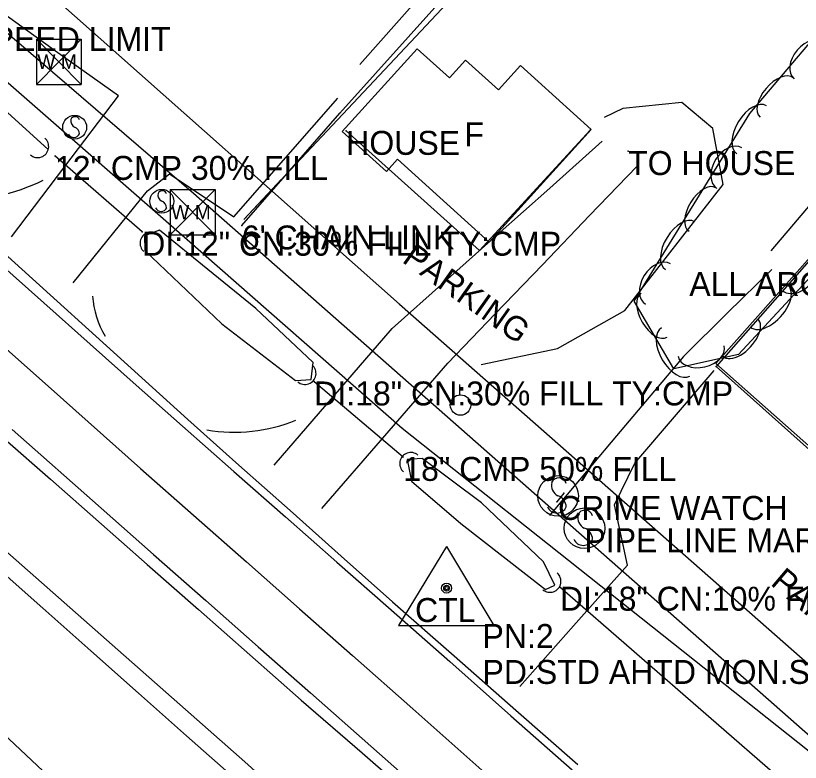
# Model space of a CAD drawing. Extents: x 1441650 to 1491889, y 345904 to 358319.
# Drawn here: x 1443948.5 to 1444112.3, y 355867 to 356022.9 of the extents above; entities that cross this region are included whole.
import ezdxf

# ---------------------------------------------------------------- set-up
doc = ezdxf.new("R2010")
doc.units = 0
for name, color, linetype in [('S_BUILDING', 7, 'Continuous'), ('S_BUILDING_ANNOT', 7, 'Continuous'), ('S_CROSS_DRAIN', 7, 'Continuous'), ('S_CROSS_DRAIN_ANNOT', 7, 'Continuous'), ('S_DITCHLINE', 7, 'Continuous'), ('S_DRG_PT_SYM', 7, 'Continuous'), ('S_EDGE_PAVEMENT', 7, 'Continuous'), ('S_FENCE', 7, 'Continuous'), ('S_FENCE_ANNOT', 7, 'Continuous'), ('S_GAS_UTILITIES', 7, 'Continuous'), ('S_GRAVEL_ROAD', 7, 'Continuous'), ('S_MSC_PT_SYM', 7, 'Continuous'), ('S_PARKING', 7, 'Continuous'), ('S_PARKING_ANNOT', 7, 'Continuous'), ('S_PAVEMENT_CROWN', 7, 'Continuous'), ('S_PRIMARY_CTL', 7, 'Continuous'), ('S_PRIMARY_CTL_ANNOT', 7, 'Continuous'), ('S_SANITARY_SEWER', 7, 'Continuous'), ('S_SHOULDER', 7, 'Continuous'), ('S_SIGN', 7, 'Continuous'), ('S_SIGN_ANNOT', 7, 'Continuous'), ('S_STR_PT_SYM', 7, 'Continuous'), ('S_STREAM', 7, 'Continuous'), ('S_SURVEY_TEXT_ANNOT', 7, 'Continuous'), ('S_TREE', 7, 'Continuous'), ('S_UTILITY_POLE', 7, 'Continuous'), ('S_UTL_PT_SYM', 7, 'Continuous'), ('S_WATER_UTILITIES', 7, 'Continuous')]:
    doc.layers.add(name, color=color, linetype=linetype)

msp = doc.modelspace()

# ---------------------------------------------------------------- linework, layer by layer
at = {"layer": 'S_BUILDING'}
for p, q in [((1444146.12, 356008.07), (1444094.68, 355949.69)), ((1444017.47, 355998.87), (1444045.28, 355973.87)), ((1444045.28, 355973.87), (1444068.39, 355999.05)), ((1444094.68, 355949.69), (1444124.92, 355922.65))]:
    msp.add_line(p, q, dxfattribs=at)
for points in [[(1444028.2, 355992.97), (1444047.33, 355975.65), (1444068.59, 355999.14), (1444053.84, 356012.49), (1444049.26, 356007.43), (1444042.38, 356013.66), (1444039.01, 356009.93), (1444032.29, 356016.01), (1444016.66, 355998.74), (1444025.88, 355990.4)], [(1444147.71, 356010.18), (1444094.63, 355950.31), (1444125.52, 355922.93), (1444178.59, 355982.81)]]:
    msp.add_lwpolyline(points, close=True, dxfattribs=at)
at = {"layer": 'S_CROSS_DRAIN'}
for p, q in [((1443974.88, 355977.81), (1443956.66, 355993.64)), ((1444010.79, 355946.55), (1444029.39, 355930.8)), ((1444062.09, 355903.7), (1444133.67, 355841.44))]:
    msp.add_line(p, q, dxfattribs=at)
for centre, start, end in [((1443953.06, 355995.6), 229.3018, 49.631), ((1443976.73, 355975.44), 49.3018, 229.631), ((1444008.87, 355948.24), 229.3018, 49.631), ((1444030.94, 355929.43), 49.3018, 229.631), ((1444060.01, 355904.83), 229.3018, 49.631)]:
    msp.add_arc(centre, 2.3, start, end, dxfattribs=at)
at = {"layer": 'S_DITCHLINE'}
for points in [[(1443680.55, 356237.92), (1443694.76, 356224.43), (1443704.6, 356215.46), (1443714.45, 356206.48), (1443724.29, 356197.51), (1443734.14, 356188.54), (1443743.98, 356179.56), (1443753.82, 356170.59), (1443763.67, 356161.61), (1443773.51, 356152.64), (1443791.44, 356137.07), (1443809.37, 356121.49), (1443827.3, 356105.92), (1443845.23, 356090.35), (1443857.24, 356080), (1443869.26, 356069.66), (1443881.27, 356059.31), (1443893.28, 356048.97), (1443905.29, 356038.62), (1443917.31, 356028.27), (1443929.32, 356017.93), (1443941.33, 356007.58), (1443955.28, 355994.97)], [(1443826.55, 356014.88), (1443833.1, 356010), (1443843.48, 356000.98), (1443853.85, 355991.95), (1443864.23, 355982.93), (1443874.61, 355973.9), (1443884.99, 355964.88), (1443895.37, 355955.85), (1443905.75, 355946.83), (1443916.13, 355937.8), (1443926.15, 355928.97), (1443936.17, 355920.13), (1443946.2, 355911.3), (1443956.22, 355902.47), (1443966.25, 355893.63), (1443976.27, 355884.8), (1443986.3, 355875.97), (1443996.32, 355867.13), (1444014.12, 355851.09), (1444031.92, 355835.05), (1444034.69, 355828.12)], [(1443825.3, 356012.13), (1443831.07, 356008.03), (1443841.45, 355998.86), (1443851.83, 355989.7), (1443862.2, 355980.53), (1443872.58, 355971.37), (1443882.96, 355962.2), (1443893.34, 355953.04), (1443903.72, 355943.87), (1443914.1, 355934.71), (1443924.1, 355925.83), (1443934.11, 355916.96), (1443944.12, 355908.09), (1443954.13, 355899.22), (1443964.13, 355890.35), (1443974.14, 355881.47), (1443984.15, 355872.6), (1443994.15, 355863.73), (1444010.59, 355846.19), (1444027.03, 355828.64), (1444031.97, 355825.21)], [(1444106.31, 355969.94), (1444097.09, 355960.86), (1444087.88, 355951.78), (1444073.9, 355935.18), (1444059.93, 355918.58)]]:
    msp.add_lwpolyline(points, dxfattribs=at)
for points in [[(1443978.52, 355978.11), (1443975.37, 355976.98), (1443975.4, 355973.87), (1443991.5, 355958.58), (1444006.86, 355946.74), (1444010.19, 355947), (1444010.6, 355950.53), (1443998.59, 355961.77), (1443988.55, 355969.94)], [(1444061.01, 355904.02), (1444058.68, 355908.93), (1444045.74, 355921.23), (1444033.32, 355930.5), (1444030.23, 355930.23), (1444031.13, 355925.71), (1444041.38, 355916.93), (1444059.11, 355903.15)]]:
    msp.add_lwpolyline(points, close=True, dxfattribs=at)
at = {"layer": 'S_DRG_PT_SYM'}
for points in [[(1443956.66, 355993.64), (1443956.66, 355993.69), (1443956.66, 355993.64), (1443956.61, 355993.64), (1443956.66, 355993.64), (1443956.66, 355993.59), (1443956.66, 355993.64), (1443956.71, 355993.64)], [(1443974.88, 355977.81), (1443974.88, 355977.86), (1443974.88, 355977.81), (1443974.83, 355977.81), (1443974.88, 355977.81), (1443974.88, 355977.76), (1443974.88, 355977.81), (1443974.93, 355977.81)], [(1444010.79, 355946.55), (1444010.79, 355946.6), (1444010.79, 355946.55), (1444010.74, 355946.55), (1444010.79, 355946.55), (1444010.79, 355946.5), (1444010.79, 355946.55), (1444010.84, 355946.55)], [(1444029.39, 355930.8), (1444029.39, 355930.85), (1444029.39, 355930.8), (1444029.34, 355930.8), (1444029.39, 355930.8), (1444029.39, 355930.75), (1444029.39, 355930.8), (1444029.44, 355930.8)], [(1444062.09, 355903.7), (1444062.09, 355903.75), (1444062.09, 355903.7), (1444062.04, 355903.7), (1444062.09, 355903.7), (1444062.09, 355903.65), (1444062.09, 355903.7), (1444062.14, 355903.7)]]:
    msp.add_lwpolyline(points, dxfattribs=at)
at = {"layer": 'S_EDGE_PAVEMENT'}
for points in [[(1443944.7, 355971.51), (1443954.35, 355962.94), (1443964, 355954.36), (1443973.65, 355945.79), (1443983.29, 355937.22), (1443994.04, 355927.76), (1444004.79, 355918.3), (1444015.54, 355908.83), (1444026.29, 355899.37), (1444039.08, 355888.06), (1444051.87, 355876.75), (1444064.66, 355865.45)], [(1443947.7, 355936.5), (1443966.34, 355920.1), (1443977.26, 355910.45), (1443988.18, 355900.81), (1443999.09, 355891.17), (1444010.01, 355881.53), (1444022.6, 355870.39), (1444035.18, 355859.26)]]:
    msp.add_lwpolyline(points, dxfattribs=at)
at = {"layer": 'S_FENCE'}
for p, q in [((1444016.14, 356002.59), (1444095, 356090.34)), ((1443995.68, 355979.12), (1444016.14, 356002.59))]:
    msp.add_line(p, q, dxfattribs=at)
for points in [[(1444095.65, 356092.67), (1444041.75, 356028.99), (1443996.1, 355980.38)], [(1444003.99, 355988.78), (1443996.1, 355980.38)]]:
    msp.add_lwpolyline(points, dxfattribs=at)
at = {"layer": 'S_GAS_UTILITIES'}
for p, q in [((1443849.94, 356102.4), (1443985.61, 355985.85)), ((1443985.61, 355985.85), (1444831.24, 355240.87))]:
    msp.add_line(p, q, dxfattribs=at)
at = {"layer": 'S_GRAVEL_ROAD'}
for points in [[(1443947.57, 355976.72), (1443958.75, 355991.45), (1443969.93, 356006.18), (1443957.29, 356015.2), (1443944.64, 356024.21), (1443932, 356033.22), (1443919.36, 356042.23), (1443907.76, 356051.97), (1443896.15, 356061.71), (1443884.55, 356071.46), (1443872.95, 356081.2), (1443854.94, 356094.72), (1443869.55, 356111.24), (1443884.15, 356127.77), (1443897.18, 356130.17), (1443918.05, 356122.57), (1443938.92, 356114.97)], [(1443960.49, 355967.18), (1443975.99, 355986.38), (1443980.58, 355989.9), (1443993.99, 355980.96), (1444004.86, 355993.34), (1444015.73, 356005.72)], [(1444002.4, 355929.1), (1444014.72, 355943.35), (1444027.04, 355957.6), (1444038.01, 355967.37), (1444048.99, 355977.15), (1444059.96, 355986.92), (1444070.93, 355996.7)], [(1444012.37, 355920.06), (1444025.54, 355935.23), (1444038.71, 355950.4), (1444048.56, 355960.67), (1444058.42, 355970.93), (1444068.27, 355981.2), (1444078.13, 355991.47)], [(1444053.74, 355882.87), (1444064.95, 355895.53), (1444076.17, 355908.2), (1444073.46, 355920.79), (1444077.75, 355929.52), (1444086.02, 355939.18), (1444094.3, 355948.84)]]:
    msp.add_lwpolyline(points, dxfattribs=at)
at = {"layer": 'S_MSC_PT_SYM'}
for points in [[(1444016.14, 356002.59), (1444016.14, 356002.64), (1444016.14, 356002.59), (1444016.09, 356002.59), (1444016.14, 356002.59), (1444016.14, 356002.54), (1444016.14, 356002.59), (1444016.19, 356002.59)], [(1444076.33, 355994.65), (1444076.33, 355994.7), (1444076.33, 355994.65), (1444076.28, 355994.65), (1444076.33, 355994.65), (1444076.33, 355994.6), (1444076.33, 355994.65), (1444076.38, 355994.65)], [(1443995.68, 355979.12), (1443995.68, 355979.17), (1443995.68, 355979.12), (1443995.63, 355979.12), (1443995.68, 355979.12), (1443995.68, 355979.07), (1443995.68, 355979.12), (1443995.73, 355979.12)], [(1444062.91, 355923.22), (1444062.91, 355923.27), (1444062.91, 355923.22), (1444062.86, 355923.22), (1444062.91, 355923.22), (1444062.91, 355923.17), (1444062.91, 355923.22), (1444062.96, 355923.22)], [(1444061.48, 355921.42), (1444061.48, 355921.47), (1444061.48, 355921.42), (1444061.43, 355921.42), (1444061.48, 355921.42), (1444061.48, 355921.37), (1444061.48, 355921.42), (1444061.53, 355921.42)]]:
    msp.add_lwpolyline(points, dxfattribs=at)
at = {"layer": 'S_PARKING'}
for points in [[(1444059.43, 356066.34), (1444064.08, 356062.11), (1444020.32, 356012.75)], [(1444045.68, 355950.13), (1444061.62, 355953.41), (1444075.63, 355961.34), (1444096.14, 355987.66), (1444094.05, 355999.37), (1444087.55, 356004.82), (1444075.2, 356003.53), (1444071.34, 356001.64)]]:
    msp.add_lwpolyline(points, dxfattribs=at)
for centre, major_axis, ratio, start_param, end_param in [((1443935.86, 356026.93), (38.83, 20.8), 0.965216, 4.220444, 4.668072), ((1443983.02, 355965.48), (-13.68, 12.57), 0.993891, 0.806764, 1.282027), ((1443994.12, 355970.42), (7.62, -33.61), 0.998476, 5.893169, 6.443204)]:
    msp.add_ellipse(centre, major_axis=major_axis, ratio=ratio, start_param=start_param, end_param=end_param, dxfattribs=at)
at = {"layer": 'S_PAVEMENT_CROWN'}
msp.add_lwpolyline([(1443937.16, 355961.6), (1443955.85, 355945), (1443974.54, 355928.4), (1443985.61, 355918.63), (1443996.68, 355908.87), (1444007.75, 355899.1), (1444018.81, 355889.33), (1444031.35, 355878.21), (1444043.89, 355867.08), (1444056.43, 355855.96)], dxfattribs=at)
at = {"layer": 'S_PRIMARY_CTL'}
for p, q in [((1444038.43, 355912.11), (1444028.4, 355895.6)), ((1444038.43, 355912.11), (1444048.26, 355895.6)), ((1444028.4, 355895.6), (1444048.26, 355895.6))]:
    msp.add_line(p, q, dxfattribs=at)
for radius in [1.04, 0.609, 0.344]:
    msp.add_circle((1444038.43, 355903.41), radius, dxfattribs=at)
at = {"layer": 'S_SANITARY_SEWER'}
for p, q in [((1443870.49, 356103.13), (1444028.57, 355962.69)), ((1443781.62, 356027.57), (1443955.36, 355864.1)), ((1444028.57, 355962.69), (1444201.27, 355810.66))]:
    msp.add_line(p, q, dxfattribs=at)
at = {"layer": 'S_SHOULDER'}
for points in [[(1443946.06, 355973.35), (1443955.64, 355964.67), (1443965.23, 355955.99), (1443974.82, 355947.31), (1443984.41, 355938.63), (1443995.08, 355929.11), (1444005.76, 355919.59), (1444016.44, 355910.07), (1444027.11, 355900.56), (1444040.02, 355889.24), (1444052.92, 355877.93), (1444065.83, 355866.61)], [(1443946.21, 355934.49), (1443955.71, 355926.14), (1443965.2, 355917.8), (1443975.93, 355908.36), (1443986.65, 355898.92), (1443997.37, 355889.48), (1444008.1, 355880.04), (1444020.78, 355868.99), (1444033.46, 355857.94)]]:
    msp.add_lwpolyline(points, dxfattribs=at)
at = {"layer": 'S_SIGN'}
msp.add_line((1444062.91, 355923.22), (1444061.48, 355921.42), dxfattribs=at)
for centre, radius in [((1443960.78, 355999.62), 2.49), ((1443978.99, 355984.17), 2.49), ((1444061.71, 355922.65), 4.24), ((1444067.21, 355915.91), 4.24)]:
    msp.add_circle(centre, radius, dxfattribs=at)
for centre, radius, start, end in [((1443961.47, 356000.95), 1.5, 167.1196, 241.9813), ((1443960.86, 356000.89), 0.95, 16.5258, 156.8957), ((1443960.37, 355998.28), 1.4, 358.6529, 73.7063), ((1443960.63, 355998.8), 1.28, 204.641, 335.359), ((1443979.06, 355985.44), 0.95, 16.5258, 156.8957), ((1443979.67, 355985.5), 1.5, 167.1196, 241.9813), ((1443978.57, 355982.83), 1.4, 358.6529, 73.7063), ((1443978.83, 355983.35), 1.28, 204.641, 335.359), ((1444061.84, 355924.81), 1.62, 16.5258, 156.8957), ((1444062.88, 355924.91), 2.55, 167.1196, 241.9813), ((1444061.01, 355920.37), 2.38, 358.6529, 73.7063), ((1444061.45, 355921.26), 2.17, 204.641, 335.359), ((1444067.34, 355918.07), 1.62, 16.5258, 156.8957), ((1444068.38, 355918.16), 2.55, 167.1196, 241.9813), ((1444066.51, 355913.63), 2.38, 358.6529, 73.7063), ((1444066.95, 355914.51), 2.17, 204.641, 335.359)]:
    msp.add_arc(centre, radius, start, end, dxfattribs=at)
at = {"layer": 'S_STR_PT_SYM'}
for points in [[(1444017.47, 355998.87), (1444017.47, 355998.92), (1444017.47, 355998.87), (1444017.42, 355998.87), (1444017.47, 355998.87), (1444017.47, 355998.82), (1444017.47, 355998.87), (1444017.52, 355998.87)], [(1444068.39, 355999.05), (1444068.39, 355999.1), (1444068.39, 355999.05), (1444068.34, 355999.05), (1444068.39, 355999.05), (1444068.39, 355999), (1444068.39, 355999.05), (1444068.44, 355999.05)], [(1444045.28, 355973.87), (1444045.28, 355973.92), (1444045.28, 355973.87), (1444045.23, 355973.87), (1444045.28, 355973.87), (1444045.28, 355973.82), (1444045.28, 355973.87), (1444045.33, 355973.87)], [(1444094.68, 355949.69), (1444094.68, 355949.74), (1444094.68, 355949.69), (1444094.63, 355949.69), (1444094.68, 355949.69), (1444094.68, 355949.64), (1444094.68, 355949.69), (1444094.73, 355949.69)]]:
    msp.add_lwpolyline(points, dxfattribs=at)
at = {"layer": 'S_STREAM'}
msp.add_lwpolyline([(1444106.2, 355973.81), (1444132.52, 356004.83)], dxfattribs=at)
at = {"layer": 'S_TREE'}
msp.add_lwpolyline([(1444178.64, 356030.05), (1444156.37, 356008.83), (1444132.49, 355987.9), (1444099.38, 355952.21), (1444085.87, 355949.17), (1444077.58, 355963.34), (1444101.72, 356002.52), (1444127.94, 356033.42), (1444120.85, 356053.53), (1444095.92, 356074.69), (1444073.13, 356101.81), (1444070.51, 356123.9)], dxfattribs=at)
for centre, major_axis, ratio, start_param, end_param in [((1444114.19, 356013.53), (-3.21, -3.78), 0.685248, 3.141603, 6.283195), ((1444107.33, 356005.85), (-3.46, -4.08), 0.54065, 3.141599, 6.283191), ((1444102.11, 355999.11), (-3.08, -5), 0.55002, 3.141593, 6.283185), ((1444097.48, 355991.09), (-2.6, -4.22), 0.685237, 3.141593, 6.283185), ((1444091.85, 355982.45), (-2.8, -4.55), 0.540641, 3.141593, 6.283185), ((1444087.2, 355974.9), (-3.08, -5), 0.55002, 3.141593, 6.283185), ((1444082.57, 355966.88), (-2.6, -4.22), 0.685237, 3.141593, 6.283185), ((1444111.9, 355969.2), (3.37, 3.63), 0.685281, 3.141436, 6.283029), ((1444105.79, 355962.24), (3.99, 4.3), 0.550056, 3.141497, 6.28309), ((1444081.77, 355960.38), (2.7, -4.61), 0.540655, 3.141593, 6.283185), ((1444099.76, 355955.74), (3.64, 3.92), 0.540676, 3.1415, 6.283093), ((1444086.25, 355952.72), (2.96, -5.06), 0.550035, 3.141593, 6.283185), ((1444091.58, 355952.9), (4.83, 1.09), 0.6853, 3.141593, 6.283185)]:
    msp.add_ellipse(centre, major_axis=major_axis, ratio=ratio, start_param=start_param, end_param=end_param, dxfattribs=at)
at = {"layer": 'S_UTILITY_POLE'}
msp.add_line((1444041.21, 355943.78), (1444041.21, 355945.89), dxfattribs=at)
msp.add_circle((1444041.33, 355941.64), 2.13, dxfattribs=at)
at = {"layer": 'S_UTL_PT_SYM'}
for points in [[(1443985.61, 355985.85), (1443985.61, 355985.9), (1443985.61, 355985.85), (1443985.56, 355985.85), (1443985.61, 355985.85), (1443985.61, 355985.8), (1443985.61, 355985.85), (1443985.66, 355985.85)], [(1443984.24, 355976.18), (1443984.24, 355976.23), (1443984.24, 355976.18), (1443984.19, 355976.18), (1443984.24, 355976.18), (1443984.24, 355976.13), (1443984.24, 355976.18), (1443984.29, 355976.18)], [(1444028.57, 355962.69), (1444028.57, 355962.74), (1444028.57, 355962.69), (1444028.52, 355962.69), (1444028.57, 355962.69), (1444028.57, 355962.64), (1444028.57, 355962.69), (1444028.62, 355962.69)], [(1444029.18, 355936.81), (1444029.18, 355936.86), (1444029.18, 355936.81), (1444029.13, 355936.81), (1444029.18, 355936.81), (1444029.18, 355936.76), (1444029.18, 355936.81), (1444029.23, 355936.81)]]:
    msp.add_lwpolyline(points, dxfattribs=at)
at = {"layer": 'S_WATER_UTILITIES'}
for p, q in [((1443843.76, 356099.08), (1443984.24, 355976.18)), ((1443952.79, 356018.05), (1443962.13, 356018.05)), ((1443952.79, 356018.05), (1443952.79, 356008.56)), ((1443952.79, 356018.05), (1443962.13, 356008.56)), ((1443962.13, 356018.05), (1443952.79, 356008.56)), ((1443962.13, 356018.05), (1443962.13, 356008.56)), ((1443952.79, 356008.56), (1443962.13, 356008.56)), ((1443980.74, 355986.66), (1443990.08, 355986.66)), ((1443980.74, 355986.66), (1443980.74, 355977.17)), ((1443980.74, 355986.66), (1443990.08, 355977.17)), ((1443990.08, 355986.66), (1443980.74, 355977.17)), ((1443990.08, 355986.66), (1443990.08, 355977.17)), ((1443980.74, 355977.17), (1443990.08, 355977.17)), ((1443984.24, 355976.18), (1444029.18, 355936.81)), ((1444029.18, 355936.81), (1444171.33, 355823.93))]:
    msp.add_line(p, q, dxfattribs=at)

# ---------------------------------------------------------------- texts
at = {"layer": 'S_BUILDING_ANNOT'}
for s, height, p in [('F', 5, (1444042.15, 355995.66)), ('HOUSE', 5, (1444017.47, 355993.87)), ('ALL AROUND AUTOMOTIVE', 5.0003, (1444089.1, 355964.4))]:
    msp.add_text(s, height=height, dxfattribs=at).set_placement(p)
at = {"layer": 'S_CROSS_DRAIN_ANNOT'}
for s, p in [('12" CMP 30% FILL', (1443956.66, 355988.64)), ('DI:12" CN:30% FILL TY:CMP', (1443974.88, 355972.81)), ('DI:18" CN:30% FILL TY:CMP', (1444010.79, 355941.55)), ('18" CMP 50% FILL', (1444029.39, 355925.8)), ('DI:18" CN:10% FILL TY:STEEL PIP', (1444062.09, 355898.7))]:
    msp.add_text(s, height=5, dxfattribs=at).set_placement(p)
at = {"layer": 'S_FENCE_ANNOT'}
msp.add_text("6' CHAIN LINK", height=5, dxfattribs=at).set_placement((1443995.68, 355974.12))
at = {"layer": 'S_PARKING_ANNOT'}
for rotation, p in [(324.716, (1444028.93, 355971.58)), (319.6773, (1444105.86, 355904.22))]:
    msp.add_text('PARKING', height=5, rotation=rotation, dxfattribs=at).set_placement(p)
at = {"layer": 'S_PRIMARY_CTL'}
msp.add_text('CTL', height=5, rotation=360, dxfattribs=at).set_placement((1444031.84, 355896.34))
at = {"layer": 'S_PRIMARY_CTL_ANNOT'}
for s, p in [('PN:2', (1444045.93, 355890.91)), ('PD:STD AHTD MON.STAMPED PN:2 JOB 050264', (1444045.93, 355883.41))]:
    msp.add_text(s, height=5, dxfattribs=at).set_placement(p)
at = {"layer": 'S_SIGN_ANNOT'}
for s, p in [('40 MPH SPEED LIMIT', (1443913.2, 356015.55)), ('CRIME WATCH', (1444061.71, 355917.65)), ('PIPE LINE MARKER CENTER POINT E', (1444067.21, 355910.91))]:
    msp.add_text(s, height=5, dxfattribs=at).set_placement(p)
at = {"layer": 'S_SURVEY_TEXT_ANNOT'}
msp.add_text('TO HOUSE', height=5, dxfattribs=at).set_placement((1444076.33, 355989.65))
at = {"layer": 'S_WATER_UTILITIES'}
for p in [(1443952.99, 356011.82), (1443980.94, 355980.43)]:
    msp.add_text('W M', height=3, rotation=360, dxfattribs=at).set_placement(p)

doc.saveas('drawing.dxf')
